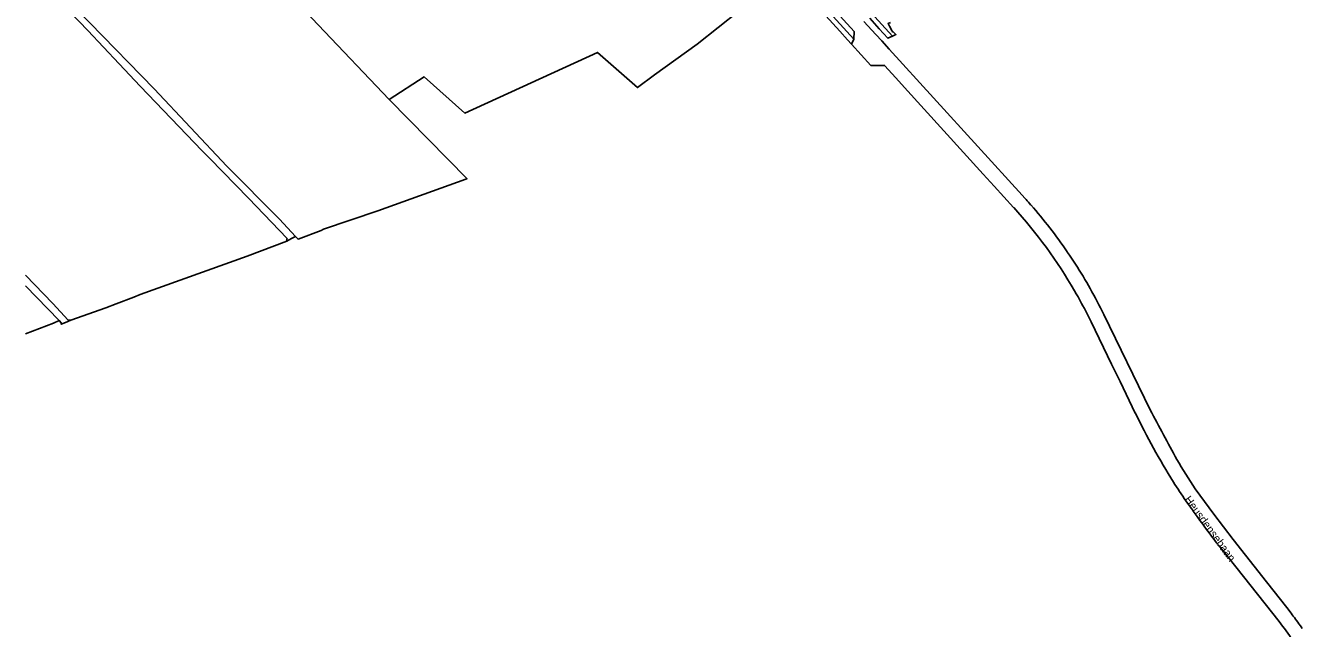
# Model space of a CAD drawing. Extents: x 141000 to 143000, y 400580 to 403500.
# Drawn here: x 141000 to 141400.1, y 401096.4 to 401284.7 of the extents above; entities that cross this region are included whole.
import ezdxf

# ---------------------------------------------------------------- set-up
doc = ezdxf.new("R2010")
doc.units = 0
for name, color, linetype in [('gg-anno-openbare ruimte label', 7, 'Continuous'), ('gg-knt-bronhoudergrens', 7, 'Continuous'), ('gg-kntw-bovenkant insteek waterloop', 7, 'Continuous'), ('gx-grn-maaiveld', 7, 'Continuous')]:
    doc.layers.add(name, color=color, linetype=linetype)

msp = doc.modelspace()

# ---------------------------------------------------------------- linework, layer by layer
at = {"layer": 'gg-knt-bronhoudergrens'}
for points in [[(141075.38, 401302.1), (141091.38, 401285.02), (141113.58, 401261.64)], [(141000, 401188.49), (141008.75, 401191.82), (141010.44, 401192.63)]]:
    msp.add_lwpolyline(points, dxfattribs=at)
at = {"layer": 'gg-kntw-bovenkant insteek waterloop'}
for points in [[(141000, 401306.35), (141040.11, 401265.03), (141062.87, 401240.86), (141079.27, 401224.25), (141084.3, 401218.89)], [(141081.57, 401217.37), (141081.64, 401217.98), (141081.67, 401218.18), (141069.67, 401230.87), (141057.52, 401243.21), (141055.11, 401245.66), (141035.83, 401265.8), (141029.24, 401272.8), (141019.42, 401283.22), (141000, 401303.46)], [(141000, 401206.83), (141008.46, 401197.92), (141013.34, 401192.77), (141014.16, 401192.67)], [(141000, 401203.46), (141006.99, 401196.21), (141010.44, 401192.63)]]:
    msp.add_lwpolyline(points, dxfattribs=at)
at = {"layer": 'gx-grn-maaiveld'}
for p, q in [((141257.98, 401278.91), (141258.72, 401280.46)), ((141351.37, 401164.71), (141336.83, 401194.5)), ((141373.69, 401121.18), (141391.61, 401098.59))]:
    msp.add_line(p, q, dxfattribs=at)
for points in [[(141153.42, 401410.26), (141214.82, 401342.93), (141216.62, 401340.94), (141270.87, 401281.45)], [(141258.72, 401280.46), (141200.12, 401344.84), (141198.47, 401346.65)], [(141258.72, 401280.46), (141258.84, 401282.88), (141201.37, 401345.93), (141199.75, 401347.7)], [(141113.58, 401261.64), (141124.51, 401268.71), (141137.26, 401257.41), (141178.62, 401276.35), (141191.14, 401265.39), (141196.52, 401269.31), (141209.78, 401278.95), (141236.03, 401299.91), (141217.23, 401319.81), (141197.76, 401341.21), (141197.05, 401342.57), (141194.68, 401340.99), (141193.24, 401342.55), (141195.66, 401344.42)], [(141197.28, 401345.67), (141198.95, 401343.84), (141254.34, 401282.99), (141256.77, 401280.26), (141257.98, 401278.91)], [(141263.71, 401287.01), (141266.71, 401283.71), (141269.38, 401280.79), (141270.87, 401281.45)], [(141261.92, 401286.04), (141265.66, 401281.93), (141267.48, 401279.93), (141269.8, 401277.38), (141311.31, 401231.78), (141312.17, 401230.83), (141312.59, 401230.37), (141312.92, 401230), (141313.34, 401229.53), (141313.67, 401229.16), (141314.08, 401228.69)], [(141270.87, 401281.45), (141271.9, 401281.91), (141270.99, 401282.83), (141270.86, 401282.77), (141270.63, 401283.19), (141269.85, 401284.61), (141269.43, 401285.38), (141270.25, 401285.75)], [(141257.98, 401278.91), (141264.07, 401272.29), (141266.21, 401272.29), (141268.33, 401272.29), (141271.88, 401268.39), (141274.61, 401265.39), (141299.18, 401238.36), (141302.57, 401234.63), (141308.68, 401227.92)], [(141084.3, 401218.89), (141085.12, 401218.01), (141092.36, 401220.73), (141093.07, 401221.14), (141110.08, 401226.88), (141137.56, 401236.79), (141137.9, 401236.92), (141113.58, 401261.64)], [(141081.57, 401217.37), (141083.08, 401218.21), (141084.3, 401218.89)], [(141014.16, 401192.67), (141025.02, 401196.54), (141028.26, 401197.79), (141033.8, 401199.92), (141035.82, 401200.7), (141069.23, 401212.69), (141081.57, 401217.37)], [(141332.59, 401202.57), (141332.04, 401203.54), (141331.49, 401204.5), (141330.92, 401205.46), (141330.35, 401206.42), (141329.77, 401207.37), (141329.19, 401208.31), (141328.6, 401209.26), (141328, 401210.2), (141327.4, 401211.13), (141326.79, 401212.06), (141326.17, 401212.99), (141325.55, 401213.91), (141325.44, 401214.06)], [(141327.71, 401201.88), (141328.25, 401200.93), (141328.79, 401199.98), (141329.32, 401199.02), (141329.44, 401198.8)], [(141010.44, 401192.63), (141011.11, 401191.93), (141011.12, 401191.44), (141012.44, 401191.97), (141014.16, 401192.67)], [(141332.86, 401192.19), (141339.26, 401179.01), (141341.91, 401173.57), (141346.69, 401163.72)], [(141398.86, 401096.44), (141398.49, 401096.95), (141398.27, 401097.24), (141397.82, 401097.87), (141397.45, 401098.37), (141397.08, 401098.88), (141396.78, 401099.29), (141396.41, 401099.79), (141396.03, 401100.31), (141395.73, 401100.71), (141395.36, 401101.21), (141394.02, 401103), (141387.69, 401110.99), (141377.25, 401124.17), (141371.17, 401132.07), (141365.37, 401140.03)], [(141362.49, 401136.33), (141363.04, 401135.53), (141363.35, 401135.09), (141363.61, 401134.72), (141363.9, 401134.3), (141364.21, 401133.86), (141364.5, 401133.45), (141364.77, 401133.07), (141365.08, 401132.63), (141365.65, 401131.84), (141365.96, 401131.41), (141366.39, 401130.81), (141366.53, 401130.62), (141366.85, 401130.19), (141367.42, 401129.4)]]:
    msp.add_lwpolyline(points, dxfattribs=at)
for centre, radius, start, end in [((141196.6, 401126.01), 151.48, 30.0563, 42.2761), ((141197.7, 401126.62), 154.81, 34.3945, 41.2535), ((141197.89, 401126.68), 154.61, 26.0193, 29.3953), ((141194.94, 401125.14), 153.35, 25.9247, 28.7063), ((141558.36, 401266.4), 235.26, 205.8789, 211.8776), ((141772.31, 401380.82), 473.17, 207.1756, 209.3045), ((141496.39, 401227.36), 157.46, 209.7498, 213.682), ((141596.65, 401297.54), 284.29, 213.1328, 214.5464), ((141594.75, 401296.34), 282.04, 216.2914, 218.3924), ((141116.29, 400892.3), 344.03, 34.4068, 36.8425)]:
    msp.add_arc(centre, radius, start, end, dxfattribs=at)

# ---------------------------------------------------------------- texts
at = {"layer": 'gg-anno-openbare ruimte label'}
msp.add_text('Heusdensebaan', height=2.5, rotation=306.2, dxfattribs=at).set_placement((141361.84, 401136.69))

doc.saveas('drawing.dxf')
